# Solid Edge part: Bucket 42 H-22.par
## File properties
Title: BUCKET 42  h 22
Author: DESYS
Template: Iso Part.par
Last saved by: a.ravenna
Revision: 64
Application: Solid Edge
Stile della faccia: Model Default
Stile di riempimento: Default
Coef. of Thermal Exp: 0.0
Thermal Conductivity: 0.0
Specific Heat: 0.0
Modulus of Elasticity: 0.0
Poisson's Ratio: 0.0
Yield Stress: 0.0
Ultimate Stress: 0.0
Elongation: 0.0
Tipo di contenuto documento: 0
Accuracy: 0,990
Document Number: 8807
Revision: 0
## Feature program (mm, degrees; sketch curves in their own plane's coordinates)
lofted protrusion "unnamed LoftedProtrusion 1"
sketch for "ScavoEstrusione_2" plane through (0, 0, 220) normal (0, 0, 1) x-axis (1, 0, 0)
  circle centre (0, 0) radius 190
extrude "ScavoEstrusione_2" cut finite 195 along -normal  Treatment1_DraftAngle = 13.5 deg
sketch for "ScavoEstrusione_3" plane through (0, 0, 0) normal (0, 0, -1) x-axis (0, 1, 0)
  circle centre (0, 0) radius 140
extrude "ScavoEstrusione_3" cut finite 20 along -normal
sketch for "ScavoEstrusione_5" plane through (0, 0, 25) normal (0, 0, 1) x-axis (1, 0, 0)
  circle centre (0, 0) radius 22.5
extrude "ScavoEstrusione_5" cut finite 455 along -normal
fillet "Rotondo_1" radius 10
sketch for "unnamed Protrusion 1" #1 plane through (0, 0, 20) normal (0, 0, -1) x-axis (-1, 0, 0)
  circle centre (0, 0) radius 32.5
sketch for "unnamed Protrusion 1" #2 plane through (0, 0, 20) normal (0, 0, -1) x-axis (-1, 0, 0)
  circle centre (0, 0) radius 22.5
extrude "unnamed Protrusion 1" add to key point along +normal
fillet "Rotondo_2" radius 20
fillet "Rotondo_3" radius 10
fillet "Rotondo_4" radius 5
fillet "Rotondo_6" radius 5
fillet "Rotondo_7" radius 2
sketch for "unnamed Cutout 1" #1 plane through (0, 0, 0) normal (0, 0, -1) x-axis (1, 0, 0)
  circle centre (0, -165) radius 8
sketch for "unnamed Cutout 1" #2 plane through (0, 0, 0) normal (0, 0, -1) x-axis (1, 0, 0)
extrude "unnamed Cutout 1" cut to key point along -normal
fillet "Rotondo_10" radius 2
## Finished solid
Body 1: solid body, 26 faces, 26 edges, 0 vertices.
  Faces by surface: torus 12, plane 7, cylinder 5, cone 2
  Edges by curve: circle 26
Bounding box of the edges (mm; curved faces can reach further): 419.009 x 419.009 x 220.000, from (-209.5043, -209.5043, 0) to (209.5043, 209.5043, 220).
Cylindrical faces by radius (mm): R8 x2, R22.5 x1, R32.5 x1, R140 x1
Conical faces (half-angle, radius in mm at the cone's reference point): 5.1944 deg R210 x1, 13.5 deg R190 x1
Toroidal faces (ring radius, tube radius in mm): R10 r2 x2, R24.5 r2 x1, R30.5 r2 x1, R31.1603 r10 x1, R37.5 r5 x1, R127.4179 r20 x1, R130 r10 x1, R145 r5 x1, R185.4339 r5 x1, R193.9417 r5 x1, R204.5248 r5 x1
Planar faces by outward normal: +z 2, -z 5
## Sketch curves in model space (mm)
circle centre (0, 0, 220) radius 210
circle centre (0, 0, 0) radius 190
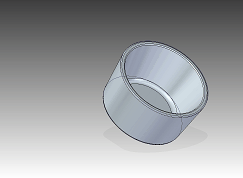
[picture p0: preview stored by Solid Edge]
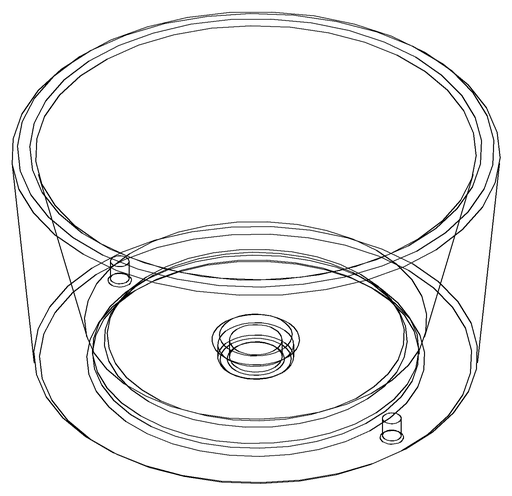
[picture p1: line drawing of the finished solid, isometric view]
